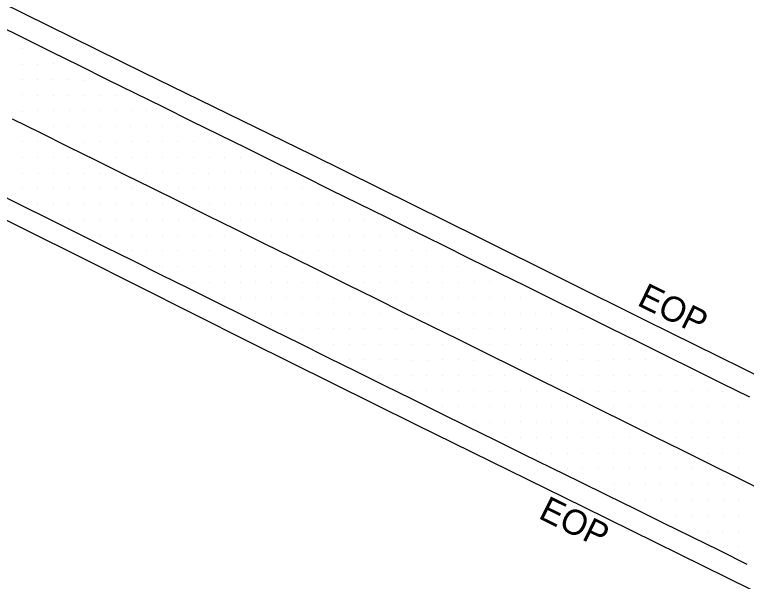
# Model space of a CAD drawing. Extents: x 2244337 to 2251208, y 199469 to 202984.
# Drawn here: x 2244517.9 to 2244635.3, y 202802.1 to 202893.2 of the extents above; entities that cross this region are included whole.
import ezdxf

# ---------------------------------------------------------------- set-up
doc = ezdxf.new("R2010")
doc.units = 0
for name, color, linetype in [('Exist DTM Scan Elevation Point', 7, 'Continuous'), ('Exist Roads EOP', 7, 'Continuous'), ('Exist Roads EOT', 7, 'Continuous'), ('Exist Roads Text', 7, 'Continuous')]:
    doc.layers.add(name, color=color, linetype=linetype)

msp = doc.modelspace()

# ---------------------------------------------------------------- linework, layer by layer
at = {"layer": 'Exist DTM Scan Elevation Point'}
for p, q in [((2244519.06, 202887.72), (2244519.06, 202887.72)), ((2244521.55, 202885.21), (2244521.55, 202885.21)), ((2244524.09, 202885.26), (2244524.09, 202885.26)), ((2244519.06, 202885.19), (2244519.06, 202885.19)), ((2244519.07, 202882.72), (2244519.07, 202882.72)), ((2244521.57, 202882.72), (2244521.57, 202882.72)), ((2244524.03, 202882.71), (2244524.03, 202882.71)), ((2244526.56, 202882.75), (2244526.56, 202882.75)), ((2244529.07, 202882.66), (2244529.07, 202882.66)), ((2244519.11, 202880.26), (2244519.11, 202880.26)), ((2244521.59, 202880.2), (2244521.59, 202880.2)), ((2244524.07, 202880.2), (2244524.07, 202880.2)), ((2244526.56, 202880.15), (2244526.56, 202880.15)), ((2244529.12, 202880.23), (2244529.12, 202880.23)), ((2244531.55, 202880.2), (2244531.55, 202880.2)), ((2244534.09, 202880.2), (2244534.09, 202880.2)), ((2244519.11, 202877.68), (2244519.11, 202877.68)), ((2244521.53, 202877.7), (2244521.53, 202877.7)), ((2244524.04, 202877.73), (2244524.04, 202877.73)), ((2244526.62, 202877.72), (2244526.62, 202877.72)), ((2244529.08, 202877.72), (2244529.08, 202877.72)), ((2244531.58, 202877.72), (2244531.58, 202877.72)), ((2244534.04, 202877.73), (2244534.04, 202877.73)), ((2244536.6, 202877.73), (2244536.6, 202877.73)), ((2244539.05, 202877.7), (2244539.05, 202877.7)), ((2244524.04, 202875.22), (2244524.04, 202875.22)), ((2244526.57, 202875.23), (2244526.57, 202875.23)), ((2244529.07, 202875.25), (2244529.07, 202875.25)), ((2244531.58, 202875.22), (2244531.58, 202875.22)), ((2244534.03, 202875.21), (2244534.03, 202875.21)), ((2244536.54, 202875.19), (2244536.54, 202875.19)), ((2244539.11, 202875.2), (2244539.11, 202875.2)), ((2244541.54, 202875.23), (2244541.54, 202875.23)), ((2244544.05, 202875.2), (2244544.05, 202875.2)), ((2244519.1, 202872.73), (2244519.1, 202872.73)), ((2244521.57, 202872.71), (2244521.57, 202872.71)), ((2244529.07, 202872.7), (2244529.07, 202872.7)), ((2244531.61, 202872.71), (2244531.61, 202872.71)), ((2244534.09, 202872.7), (2244534.09, 202872.7)), ((2244536.56, 202872.74), (2244536.56, 202872.74)), ((2244539.12, 202872.75), (2244539.12, 202872.75)), ((2244541.54, 202872.75), (2244541.54, 202872.75)), ((2244544.07, 202872.75), (2244544.07, 202872.75)), ((2244546.55, 202872.73), (2244546.55, 202872.73)), ((2244549.08, 202872.7), (2244549.08, 202872.7)), ((2244519.08, 202870.25), (2244519.08, 202870.25)), ((2244521.59, 202870.2), (2244521.59, 202870.2)), ((2244524.06, 202870.18), (2244524.06, 202870.18)), ((2244526.55, 202870.19), (2244526.55, 202870.19)), ((2244534.02, 202870.2), (2244534.02, 202870.2)), ((2244536.58, 202870.19), (2244536.58, 202870.19)), ((2244539.1, 202870.19), (2244539.1, 202870.19)), ((2244541.55, 202870.24), (2244541.55, 202870.24)), ((2244544.05, 202870.17), (2244544.05, 202870.17)), ((2244546.56, 202870.14), (2244546.56, 202870.14)), ((2244549.09, 202870.2), (2244549.09, 202870.2)), ((2244551.63, 202870.19), (2244551.63, 202870.19)), ((2244554.1, 202870.19), (2244554.1, 202870.19)), ((2244519.09, 202867.72), (2244519.09, 202867.72)), ((2244521.64, 202867.72), (2244521.64, 202867.72)), ((2244524.08, 202867.7), (2244524.08, 202867.7)), ((2244526.53, 202867.68), (2244526.53, 202867.68)), ((2244529.07, 202867.71), (2244529.07, 202867.71)), ((2244531.61, 202867.69), (2244531.61, 202867.69)), ((2244539.05, 202867.69), (2244539.05, 202867.69)), ((2244541.56, 202867.73), (2244541.56, 202867.73)), ((2244544.09, 202867.68), (2244544.09, 202867.68)), ((2244546.59, 202867.71), (2244546.59, 202867.71)), ((2244549.05, 202867.71), (2244549.05, 202867.71)), ((2244551.59, 202867.74), (2244551.59, 202867.74)), ((2244554.1, 202867.76), (2244554.1, 202867.76)), ((2244556.57, 202867.73), (2244556.57, 202867.73)), ((2244559.09, 202867.7), (2244559.09, 202867.7)), ((2244546.61, 202865.24), (2244546.61, 202865.24)), ((2244549, 202865.26), (2244549, 202865.26)), ((2244519.1, 202865.21), (2244519.1, 202865.21)), ((2244521.6, 202865.23), (2244521.6, 202865.23)), ((2244524.12, 202865.16), (2244524.12, 202865.16)), ((2244526.62, 202865.21), (2244526.62, 202865.21)), ((2244529.05, 202865.19), (2244529.05, 202865.19)), ((2244531.62, 202865.22), (2244531.62, 202865.22)), ((2244534, 202865.21), (2244534, 202865.21)), ((2244536.56, 202865.16), (2244536.56, 202865.16)), ((2244544.13, 202865.16), (2244544.13, 202865.16)), ((2244551.56, 202865.2), (2244551.56, 202865.2)), ((2244554.13, 202865.21), (2244554.13, 202865.21)), ((2244556.58, 202865.16), (2244556.58, 202865.16)), ((2244559.11, 202865.23), (2244559.11, 202865.23)), ((2244561.52, 202865.2), (2244561.52, 202865.2)), ((2244564.09, 202865.23), (2244564.09, 202865.23)), ((2244521.6, 202862.72), (2244521.6, 202862.72)), ((2244524.1, 202862.75), (2244524.1, 202862.75)), ((2244526.57, 202862.7), (2244526.57, 202862.7)), ((2244529.07, 202862.72), (2244529.07, 202862.72)), ((2244531.57, 202862.73), (2244531.57, 202862.73)), ((2244534.09, 202862.71), (2244534.09, 202862.71)), ((2244536.58, 202862.71), (2244536.58, 202862.71)), ((2244539.07, 202862.68), (2244539.07, 202862.68)), ((2244541.58, 202862.72), (2244541.58, 202862.72)), ((2244549.1, 202862.68), (2244549.1, 202862.68)), ((2244551.59, 202862.73), (2244551.59, 202862.73)), ((2244554.08, 202862.7), (2244554.08, 202862.7)), ((2244556.57, 202862.72), (2244556.57, 202862.72)), ((2244559.03, 202862.75), (2244559.03, 202862.75)), ((2244561.57, 202862.7), (2244561.57, 202862.7)), ((2244564.07, 202862.76), (2244564.07, 202862.76)), ((2244566.58, 202862.75), (2244566.58, 202862.75)), ((2244569.04, 202862.71), (2244569.04, 202862.71)), ((2244526.6, 202860.14), (2244526.6, 202860.14)), ((2244529.08, 202860.22), (2244529.08, 202860.22)), ((2244531.53, 202860.18), (2244531.53, 202860.18)), ((2244534.1, 202860.22), (2244534.1, 202860.22)), ((2244536.61, 202860.21), (2244536.61, 202860.21)), ((2244539.07, 202860.24), (2244539.07, 202860.24)), ((2244541.61, 202860.24), (2244541.61, 202860.24)), ((2244544.11, 202860.2), (2244544.11, 202860.2)), ((2244546.58, 202860.23), (2244546.58, 202860.23)), ((2244554.05, 202860.19), (2244554.05, 202860.19)), ((2244556.61, 202860.23), (2244556.61, 202860.23)), ((2244559.1, 202860.25), (2244559.1, 202860.25)), ((2244561.63, 202860.23), (2244561.63, 202860.23)), ((2244564.07, 202860.22), (2244564.07, 202860.22)), ((2244566.56, 202860.24), (2244566.56, 202860.24)), ((2244569.05, 202860.24), (2244569.05, 202860.24)), ((2244571.56, 202860.2), (2244571.56, 202860.2)), ((2244574, 202860.26), (2244574, 202860.26)), ((2244531.58, 202857.73), (2244531.58, 202857.73)), ((2244534.13, 202857.68), (2244534.13, 202857.68)), ((2244536.58, 202857.75), (2244536.58, 202857.75)), ((2244539.09, 202857.68), (2244539.09, 202857.68)), ((2244541.59, 202857.66), (2244541.59, 202857.66)), ((2244544.08, 202857.7), (2244544.08, 202857.7)), ((2244546.64, 202857.73), (2244546.64, 202857.73)), ((2244549.1, 202857.69), (2244549.1, 202857.69)), ((2244551.58, 202857.7), (2244551.58, 202857.7)), ((2244559.07, 202857.72), (2244559.07, 202857.72)), ((2244561.62, 202857.66), (2244561.62, 202857.66)), ((2244564.02, 202857.69), (2244564.02, 202857.69)), ((2244566.59, 202857.72), (2244566.59, 202857.72)), ((2244569.09, 202857.74), (2244569.09, 202857.74)), ((2244571.61, 202857.72), (2244571.61, 202857.72)), ((2244574.06, 202857.71), (2244574.06, 202857.71)), ((2244576.52, 202857.7), (2244576.52, 202857.7)), ((2244579.11, 202857.68), (2244579.11, 202857.68)), ((2244536.59, 202855.21), (2244536.59, 202855.21)), ((2244539.1, 202855.21), (2244539.1, 202855.21)), ((2244541.54, 202855.21), (2244541.54, 202855.21)), ((2244544.06, 202855.2), (2244544.06, 202855.2)), ((2244546.61, 202855.23), (2244546.61, 202855.23)), ((2244549.08, 202855.24), (2244549.08, 202855.24)), ((2244551.57, 202855.24), (2244551.57, 202855.24)), ((2244554.13, 202855.23), (2244554.13, 202855.23)), ((2244556.57, 202855.24), (2244556.57, 202855.24)), ((2244564.08, 202855.19), (2244564.08, 202855.19)), ((2244566.58, 202855.22), (2244566.58, 202855.22)), ((2244569.1, 202855.25), (2244569.1, 202855.25)), ((2244571.61, 202855.29), (2244571.61, 202855.29)), ((2244574.04, 202855.21), (2244574.04, 202855.21)), ((2244576.57, 202855.24), (2244576.57, 202855.24)), ((2244579.14, 202855.2), (2244579.14, 202855.2)), ((2244581.6, 202855.2), (2244581.6, 202855.2)), ((2244584.04, 202855.25), (2244584.04, 202855.25)), ((2244541.6, 202852.74), (2244541.6, 202852.74)), ((2244544.07, 202852.72), (2244544.07, 202852.72)), ((2244546.6, 202852.71), (2244546.6, 202852.71)), ((2244549.09, 202852.73), (2244549.09, 202852.73)), ((2244551.59, 202852.68), (2244551.59, 202852.68)), ((2244554.07, 202852.68), (2244554.07, 202852.68)), ((2244556.53, 202852.69), (2244556.53, 202852.69)), ((2244559.12, 202852.71), (2244559.12, 202852.71)), ((2244561.54, 202852.74), (2244561.54, 202852.74)), ((2244569.04, 202852.69), (2244569.04, 202852.69)), ((2244571.52, 202852.7), (2244571.52, 202852.7)), ((2244574.07, 202852.71), (2244574.07, 202852.71)), ((2244576.55, 202852.7), (2244576.55, 202852.7)), ((2244579.04, 202852.69), (2244579.04, 202852.69)), ((2244581.57, 202852.7), (2244581.57, 202852.7)), ((2244584.06, 202852.71), (2244584.06, 202852.71)), ((2244586.58, 202852.73), (2244586.58, 202852.73)), ((2244589.02, 202852.7), (2244589.02, 202852.7)), ((2244546.6, 202850.19), (2244546.6, 202850.19)), ((2244549.08, 202850.22), (2244549.08, 202850.22)), ((2244551.58, 202850.21), (2244551.58, 202850.21)), ((2244554.07, 202850.21), (2244554.07, 202850.21)), ((2244556.55, 202850.24), (2244556.55, 202850.24)), ((2244559.08, 202850.2), (2244559.08, 202850.2)), ((2244561.61, 202850.22), (2244561.61, 202850.22)), ((2244564.06, 202850.2), (2244564.06, 202850.2)), ((2244566.56, 202850.16), (2244566.56, 202850.16)), ((2244574.06, 202850.2), (2244574.06, 202850.2)), ((2244576.53, 202850.2), (2244576.53, 202850.2)), ((2244579.11, 202850.25), (2244579.11, 202850.25)), ((2244581.6, 202850.21), (2244581.6, 202850.21)), ((2244584.13, 202850.18), (2244584.13, 202850.18)), ((2244586.54, 202850.17), (2244586.54, 202850.17)), ((2244589.07, 202850.22), (2244589.07, 202850.22)), ((2244591.62, 202850.24), (2244591.62, 202850.24)), ((2244594.06, 202850.24), (2244594.06, 202850.24)), ((2244551.6, 202847.75), (2244551.6, 202847.75)), ((2244554.08, 202847.72), (2244554.08, 202847.72)), ((2244556.59, 202847.74), (2244556.59, 202847.74)), ((2244559.06, 202847.73), (2244559.06, 202847.73)), ((2244561.58, 202847.69), (2244561.58, 202847.69)), ((2244564.1, 202847.66), (2244564.1, 202847.66)), ((2244566.58, 202847.71), (2244566.58, 202847.71)), ((2244569.02, 202847.65), (2244569.02, 202847.65)), ((2244571.56, 202847.73), (2244571.56, 202847.73)), ((2244579.07, 202847.69), (2244579.07, 202847.69)), ((2244581.54, 202847.71), (2244581.54, 202847.71)), ((2244584.06, 202847.67), (2244584.06, 202847.67)), ((2244586.59, 202847.72), (2244586.59, 202847.72)), ((2244589.06, 202847.71), (2244589.06, 202847.71)), ((2244591.57, 202847.7), (2244591.57, 202847.7)), ((2244594.12, 202847.71), (2244594.12, 202847.71)), ((2244596.57, 202847.73), (2244596.57, 202847.73)), ((2244599.07, 202847.7), (2244599.07, 202847.7)), ((2244556.6, 202845.22), (2244556.6, 202845.22)), ((2244559.08, 202845.21), (2244559.08, 202845.21)), ((2244561.55, 202845.22), (2244561.55, 202845.22)), ((2244564.06, 202845.17), (2244564.06, 202845.17)), ((2244566.59, 202845.24), (2244566.59, 202845.24)), ((2244569.07, 202845.23), (2244569.07, 202845.23)), ((2244571.59, 202845.24), (2244571.59, 202845.24)), ((2244574.08, 202845.19), (2244574.08, 202845.19)), ((2244576.58, 202845.19), (2244576.58, 202845.19)), ((2244584.09, 202845.19), (2244584.09, 202845.19)), ((2244586.58, 202845.22), (2244586.58, 202845.22)), ((2244589.09, 202845.25), (2244589.09, 202845.25)), ((2244591.59, 202845.21), (2244591.59, 202845.21)), ((2244594.09, 202845.23), (2244594.09, 202845.23)), ((2244596.57, 202845.2), (2244596.57, 202845.2)), ((2244599.07, 202845.16), (2244599.07, 202845.16)), ((2244601.54, 202845.21), (2244601.54, 202845.21)), ((2244604.06, 202845.2), (2244604.06, 202845.2)), ((2244561.56, 202842.74), (2244561.56, 202842.74)), ((2244564.09, 202842.67), (2244564.09, 202842.67)), ((2244566.58, 202842.75), (2244566.58, 202842.75)), ((2244569.07, 202842.71), (2244569.07, 202842.71)), ((2244571.57, 202842.68), (2244571.57, 202842.68)), ((2244574.11, 202842.72), (2244574.11, 202842.72)), ((2244576.6, 202842.68), (2244576.6, 202842.68)), ((2244579.1, 202842.68), (2244579.1, 202842.68)), ((2244581.59, 202842.7), (2244581.59, 202842.7)), ((2244589.08, 202842.71), (2244589.08, 202842.71)), ((2244591.58, 202842.72), (2244591.58, 202842.72)), ((2244594.1, 202842.68), (2244594.1, 202842.68)), ((2244596.57, 202842.68), (2244596.57, 202842.68)), ((2244599.07, 202842.73), (2244599.07, 202842.73)), ((2244601.58, 202842.73), (2244601.58, 202842.73)), ((2244604.02, 202842.72), (2244604.02, 202842.72)), ((2244606.63, 202842.66), (2244606.63, 202842.66)), ((2244609.08, 202842.69), (2244609.08, 202842.69)), ((2244566.56, 202840.2), (2244566.56, 202840.2)), ((2244569.08, 202840.18), (2244569.08, 202840.18)), ((2244571.59, 202840.21), (2244571.59, 202840.21)), ((2244574.04, 202840.18), (2244574.04, 202840.18)), ((2244576.62, 202840.17), (2244576.62, 202840.17)), ((2244579.07, 202840.23), (2244579.07, 202840.23)), ((2244581.56, 202840.24), (2244581.56, 202840.24)), ((2244584.07, 202840.21), (2244584.07, 202840.21)), ((2244586.58, 202840.22), (2244586.58, 202840.22)), ((2244594.02, 202840.18), (2244594.02, 202840.18)), ((2244596.63, 202840.24), (2244596.63, 202840.24)), ((2244599.11, 202840.25), (2244599.11, 202840.25)), ((2244601.56, 202840.25), (2244601.56, 202840.25)), ((2244604.05, 202840.2), (2244604.05, 202840.2)), ((2244606.57, 202840.17), (2244606.57, 202840.17)), ((2244609.1, 202840.16), (2244609.1, 202840.16)), ((2244611.57, 202840.22), (2244611.57, 202840.22)), ((2244614.06, 202840.19), (2244614.06, 202840.19)), ((2244616.54, 202840.2), (2244616.54, 202840.2)), ((2244571.6, 202837.71), (2244571.6, 202837.71)), ((2244574.07, 202837.75), (2244574.07, 202837.75)), ((2244576.56, 202837.72), (2244576.56, 202837.72)), ((2244579.09, 202837.7), (2244579.09, 202837.7)), ((2244581.57, 202837.69), (2244581.57, 202837.69)), ((2244584.08, 202837.69), (2244584.08, 202837.69)), ((2244586.58, 202837.73), (2244586.58, 202837.73)), ((2244589.11, 202837.7), (2244589.11, 202837.7)), ((2244591.59, 202837.69), (2244591.59, 202837.69)), ((2244599.09, 202837.71), (2244599.09, 202837.71)), ((2244601.55, 202837.74), (2244601.55, 202837.74)), ((2244604.11, 202837.7), (2244604.11, 202837.7)), ((2244606.55, 202837.69), (2244606.55, 202837.69)), ((2244609.06, 202837.7), (2244609.06, 202837.7)), ((2244611.58, 202837.68), (2244611.58, 202837.68)), ((2244614.04, 202837.7), (2244614.04, 202837.7)), ((2244616.57, 202837.75), (2244616.57, 202837.75)), ((2244619.1, 202837.75), (2244619.1, 202837.75)), ((2244576.57, 202835.17), (2244576.57, 202835.17)), ((2244579.07, 202835.18), (2244579.07, 202835.18)), ((2244581.52, 202835.21), (2244581.52, 202835.21)), ((2244584.04, 202835.23), (2244584.04, 202835.23)), ((2244586.52, 202835.23), (2244586.52, 202835.23)), ((2244589.13, 202835.17), (2244589.13, 202835.17)), ((2244591.55, 202835.25), (2244591.55, 202835.25)), ((2244594.03, 202835.25), (2244594.03, 202835.25)), ((2244596.53, 202835.2), (2244596.53, 202835.2)), ((2244604.08, 202835.22), (2244604.08, 202835.22)), ((2244606.55, 202835.22), (2244606.55, 202835.22)), ((2244609.1, 202835.17), (2244609.1, 202835.17)), ((2244611.6, 202835.24), (2244611.6, 202835.24)), ((2244614.06, 202835.28), (2244614.06, 202835.28)), ((2244616.56, 202835.23), (2244616.56, 202835.23)), ((2244619.07, 202835.22), (2244619.07, 202835.22)), ((2244621.59, 202835.23), (2244621.59, 202835.23)), ((2244624.1, 202835.22), (2244624.1, 202835.22)), ((2244626.56, 202835.19), (2244626.56, 202835.19)), ((2244581.58, 202832.71), (2244581.58, 202832.71)), ((2244584.05, 202832.74), (2244584.05, 202832.74)), ((2244586.59, 202832.75), (2244586.59, 202832.75)), ((2244589.08, 202832.7), (2244589.08, 202832.7)), ((2244591.55, 202832.72), (2244591.55, 202832.72)), ((2244594.14, 202832.64), (2244594.14, 202832.64)), ((2244596.6, 202832.71), (2244596.6, 202832.71)), ((2244599.02, 202832.74), (2244599.02, 202832.74)), ((2244601.61, 202832.71), (2244601.61, 202832.71)), ((2244609.05, 202832.75), (2244609.05, 202832.75)), ((2244611.52, 202832.69), (2244611.52, 202832.69)), ((2244614.09, 202832.67), (2244614.09, 202832.67)), ((2244616.54, 202832.69), (2244616.54, 202832.69)), ((2244619.05, 202832.7), (2244619.05, 202832.7)), ((2244621.58, 202832.74), (2244621.58, 202832.74)), ((2244624.09, 202832.69), (2244624.09, 202832.69)), ((2244626.52, 202832.74), (2244626.52, 202832.74)), ((2244629.07, 202832.74), (2244629.07, 202832.74)), ((2244631.51, 202832.68), (2244631.51, 202832.68)), ((2244586.53, 202830.2), (2244586.53, 202830.2)), ((2244589.06, 202830.2), (2244589.06, 202830.2)), ((2244591.59, 202830.22), (2244591.59, 202830.22)), ((2244594.11, 202830.2), (2244594.11, 202830.2)), ((2244596.51, 202830.18), (2244596.51, 202830.18)), ((2244599.08, 202830.26), (2244599.08, 202830.26)), ((2244601.59, 202830.21), (2244601.59, 202830.21)), ((2244604.03, 202830.22), (2244604.03, 202830.22)), ((2244606.6, 202830.21), (2244606.6, 202830.21)), ((2244614.07, 202830.19), (2244614.07, 202830.19)), ((2244616.65, 202830.19), (2244616.65, 202830.19)), ((2244619.04, 202830.24), (2244619.04, 202830.24)), ((2244621.54, 202830.24), (2244621.54, 202830.24)), ((2244624.08, 202830.22), (2244624.08, 202830.22)), ((2244626.63, 202830.21), (2244626.63, 202830.21)), ((2244629.06, 202830.21), (2244629.06, 202830.21)), ((2244631.58, 202830.19), (2244631.58, 202830.19)), ((2244634.1, 202830.18), (2244634.1, 202830.18)), ((2244591.57, 202827.67), (2244591.57, 202827.67)), ((2244594.14, 202827.7), (2244594.14, 202827.7)), ((2244596.58, 202827.72), (2244596.58, 202827.72)), ((2244599.08, 202827.74), (2244599.08, 202827.74)), ((2244601.56, 202827.7), (2244601.56, 202827.7)), ((2244604.03, 202827.71), (2244604.03, 202827.71)), ((2244606.57, 202827.67), (2244606.57, 202827.67)), ((2244609.05, 202827.71), (2244609.05, 202827.71)), ((2244611.5, 202827.72), (2244611.5, 202827.72)), ((2244619.07, 202827.73), (2244619.07, 202827.73)), ((2244621.59, 202827.71), (2244621.59, 202827.71)), ((2244624.11, 202827.69), (2244624.11, 202827.69)), ((2244626.58, 202827.68), (2244626.58, 202827.68)), ((2244629.08, 202827.68), (2244629.08, 202827.68)), ((2244631.54, 202827.66), (2244631.54, 202827.66)), ((2244634.1, 202827.7), (2244634.1, 202827.7)), ((2244596.59, 202825.21), (2244596.59, 202825.21)), ((2244599.04, 202825.22), (2244599.04, 202825.22)), ((2244601.61, 202825.18), (2244601.61, 202825.18)), ((2244604.08, 202825.21), (2244604.08, 202825.21)), ((2244606.58, 202825.22), (2244606.58, 202825.22)), ((2244609.07, 202825.17), (2244609.07, 202825.17)), ((2244611.54, 202825.22), (2244611.54, 202825.22)), ((2244614.07, 202825.19), (2244614.07, 202825.19)), ((2244616.53, 202825.23), (2244616.53, 202825.23)), ((2244624.08, 202825.2), (2244624.08, 202825.2)), ((2244626.58, 202825.21), (2244626.58, 202825.21)), ((2244629.11, 202825.2), (2244629.11, 202825.2)), ((2244631.58, 202825.24), (2244631.58, 202825.24)), ((2244634.06, 202825.2), (2244634.06, 202825.2)), ((2244601.57, 202822.71), (2244601.57, 202822.71)), ((2244604.04, 202822.73), (2244604.04, 202822.73)), ((2244606.6, 202822.7), (2244606.6, 202822.7)), ((2244609.07, 202822.75), (2244609.07, 202822.75)), ((2244611.57, 202822.68), (2244611.57, 202822.68)), ((2244614.07, 202822.71), (2244614.07, 202822.71)), ((2244616.6, 202822.69), (2244616.6, 202822.69)), ((2244619.05, 202822.7), (2244619.05, 202822.7)), ((2244621.58, 202822.71), (2244621.58, 202822.71)), ((2244629.08, 202822.74), (2244629.08, 202822.74)), ((2244631.57, 202822.75), (2244631.57, 202822.75)), ((2244634.11, 202822.72), (2244634.11, 202822.72)), ((2244606.57, 202820.25), (2244606.57, 202820.25)), ((2244609.07, 202820.2), (2244609.07, 202820.2)), ((2244611.58, 202820.24), (2244611.58, 202820.24)), ((2244614.03, 202820.21), (2244614.03, 202820.21)), ((2244616.53, 202820.21), (2244616.53, 202820.21)), ((2244619.11, 202820.2), (2244619.11, 202820.2)), ((2244621.54, 202820.24), (2244621.54, 202820.24)), ((2244624.08, 202820.22), (2244624.08, 202820.22)), ((2244626.59, 202820.23), (2244626.59, 202820.23)), ((2244634.1, 202820.19), (2244634.1, 202820.19)), ((2244614.1, 202817.75), (2244614.1, 202817.75)), ((2244616.52, 202817.69), (2244616.52, 202817.69)), ((2244619.07, 202817.73), (2244619.07, 202817.73)), ((2244621.56, 202817.7), (2244621.56, 202817.7)), ((2244624.05, 202817.68), (2244624.05, 202817.68)), ((2244626.57, 202817.66), (2244626.57, 202817.66)), ((2244629.03, 202817.74), (2244629.03, 202817.74)), ((2244631.6, 202817.69), (2244631.6, 202817.69)), ((2244619.1, 202815.19), (2244619.1, 202815.19)), ((2244621.63, 202815.24), (2244621.63, 202815.24)), ((2244624.05, 202815.22), (2244624.05, 202815.22)), ((2244626.58, 202815.21), (2244626.58, 202815.21)), ((2244629.07, 202815.21), (2244629.07, 202815.21)), ((2244631.59, 202815.24), (2244631.59, 202815.24)), ((2244634.06, 202815.21), (2244634.06, 202815.21)), ((2244624.07, 202812.69), (2244624.07, 202812.69)), ((2244626.57, 202812.7), (2244626.57, 202812.7)), ((2244629.02, 202812.7), (2244629.02, 202812.7)), ((2244631.64, 202812.72), (2244631.64, 202812.72)), ((2244634.1, 202812.7), (2244634.1, 202812.7)), ((2244629.11, 202810.22), (2244629.11, 202810.22)), ((2244631.55, 202810.22), (2244631.55, 202810.22)), ((2244634.1, 202810.2), (2244634.1, 202810.2)), ((2244634.09, 202807.71), (2244634.09, 202807.71))]:
    msp.add_line(p, q, dxfattribs=at)
at = {"layer": 'Exist Roads EOP'}
for points in [[(2244395.66, 202954.76), (2244404.18, 202950.47), (2244431.16, 202937.33), (2244457.85, 202923.62), (2244484.86, 202910.57), (2244511.7, 202897.15), (2244538.58, 202883.85), (2244565.54, 202870.69), (2244592.44, 202857.39), (2244619.28, 202843.98), (2244646.19, 202830.72), (2244673.01, 202817.26), (2244699.8, 202803.75), (2244726.71, 202790.51), (2244753.64, 202777.29), (2244780.49, 202763.92), (2244807.36, 202750.56), (2244834.19, 202737.17), (2244861.07, 202723.84), (2244887.94, 202710.51), (2244914.92, 202697.38), (2244941.73, 202683.92)], [(2244958.85, 202641.19), (2244931.98, 202654.52), (2244905.1, 202667.85), (2244878.24, 202681.21), (2244851.36, 202694.53), (2244824.43, 202707.74), (2244797.54, 202721.05), (2244770.65, 202734.35), (2244743.76, 202747.66), (2244716.89, 202760.99), (2244690.18, 202774.66), (2244663.01, 202787.42), (2244636.15, 202800.76), (2244609.26, 202814.04), (2244582.35, 202827.29), (2244555.46, 202840.63), (2244528.66, 202854.11), (2244501.78, 202867.44), (2244474.81, 202880.57), (2244448.01, 202894.05), (2244421.03, 202907.17), (2244394.33, 202920.84), (2244380.98, 202927.4)]]:
    msp.add_lwpolyline(points, dxfattribs=at)
at = {"layer": 'Exist Roads EOT'}
for points in [[(2244514.81, 202891.64), (2244519.3, 202889.42), (2244523.78, 202887.2), (2244528.26, 202884.98), (2244532.74, 202882.77), (2244537.22, 202880.55), (2244541.7, 202878.33), (2244546.18, 202876.12), (2244550.67, 202873.9), (2244555.15, 202871.69), (2244559.63, 202869.47), (2244564.11, 202867.26), (2244568.6, 202865.04), (2244573.08, 202862.83), (2244577.56, 202860.61), (2244582.05, 202858.4), (2244586.53, 202856.18), (2244591.01, 202853.96), (2244595.49, 202851.75), (2244599.97, 202849.53), (2244604.45, 202847.31), (2244608.93, 202845.09), (2244613.42, 202842.88), (2244617.9, 202840.66), (2244622.38, 202838.44), (2244626.86, 202836.22), (2244631.34, 202833.99), (2244635.82, 202831.77)], [(2244517.47, 202876.43), (2244521.95, 202874.21), (2244526.43, 202871.99), (2244530.91, 202869.78), (2244535.39, 202867.56), (2244539.87, 202865.35), (2244544.36, 202863.13), (2244548.84, 202860.92), (2244553.32, 202858.7), (2244557.8, 202856.48), (2244562.29, 202854.27), (2244566.77, 202852.05), (2244571.25, 202849.83), (2244575.73, 202847.61), (2244580.21, 202845.39), (2244584.69, 202843.18), (2244589.17, 202840.96), (2244593.65, 202838.74), (2244598.13, 202836.52), (2244602.61, 202834.3), (2244607.09, 202832.08), (2244611.57, 202829.86), (2244616.05, 202827.64), (2244620.53, 202825.42), (2244625.01, 202823.2), (2244629.49, 202820.98), (2244633.97, 202818.76), (2244638.45, 202816.54)], [(2244635.47, 202804.85), (2244630.99, 202807.07), (2244626.51, 202809.29), (2244622.03, 202811.5), (2244617.55, 202813.72), (2244613.06, 202815.92), (2244608.57, 202818.13), (2244604.09, 202820.34), (2244599.6, 202822.54), (2244595.12, 202824.75), (2244590.63, 202826.96), (2244586.15, 202829.17), (2244581.66, 202831.38), (2244577.18, 202833.61), (2244572.7, 202835.83), (2244568.22, 202838.05), (2244563.75, 202840.28), (2244559.27, 202842.5), (2244554.79, 202844.72), (2244550.31, 202846.95), (2244545.83, 202849.17), (2244541.35, 202851.39), (2244536.88, 202853.62), (2244532.4, 202855.84), (2244527.92, 202858.06), (2244523.44, 202860.29), (2244518.96, 202862.51), (2244514.48, 202864.73)]]:
    msp.add_lwpolyline(points, dxfattribs=at)

# ---------------------------------------------------------------- texts
at = {"layer": 'Exist Roads Text'}
for p in [(2244617.62, 202846.57), (2244601.79, 202812.35)]:
    msp.add_text('EOP', height=4.02, rotation=333.7798, dxfattribs=at).set_placement(p)

doc.saveas('drawing.dxf')
